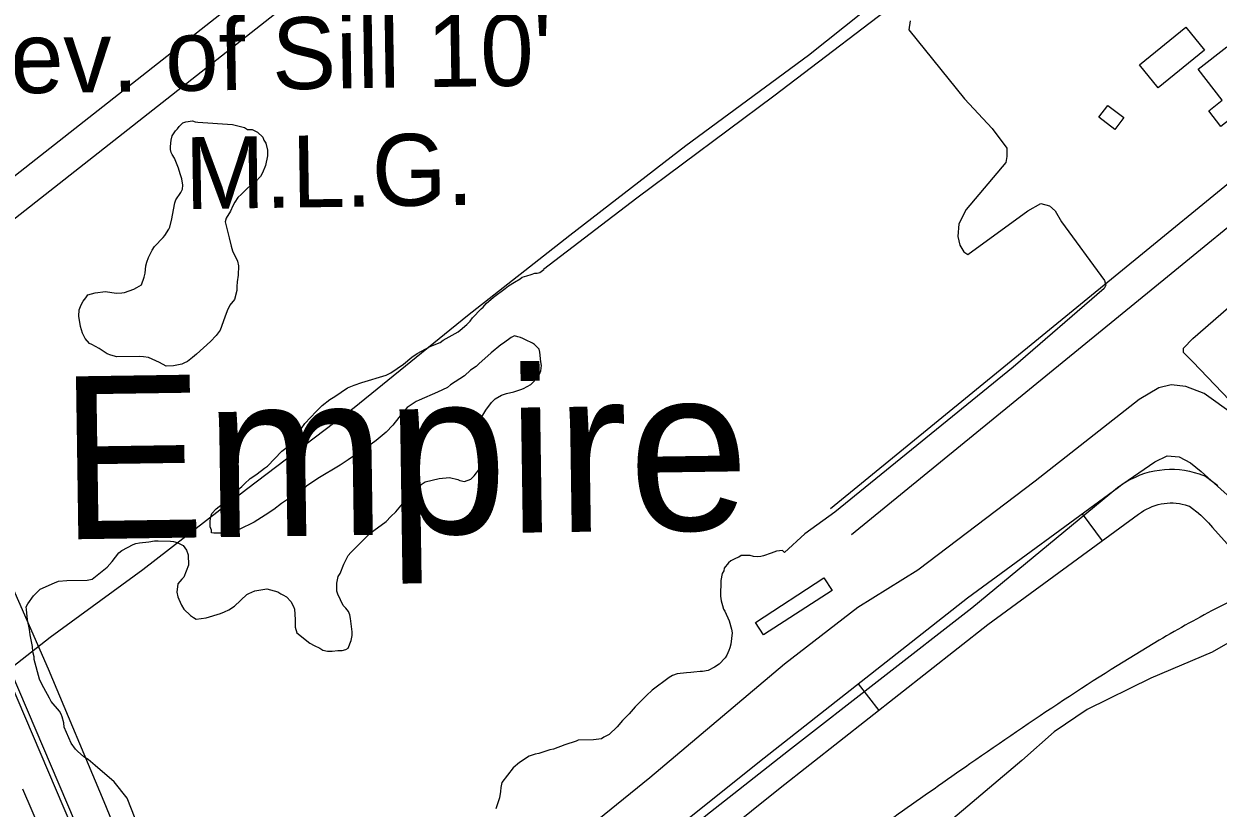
# Model space of a CAD drawing. Extents: x 3812694 to 3850888, y 319753 to 345638.
# Drawn here: x 3831459 to 3832522, y 326802 to 327501 of the extents above; entities that cross this region are included whole.
import ezdxf

# ---------------------------------------------------------------- set-up
doc = ezdxf.new("R2010")
doc.units = 0
for name, color, linetype in [('V-BLDG-OTLN', 7, 'Continuous'), ('V-BRDG-IDEN', 7, 'Continuous'), ('V-BRDG-OTLN', 7, 'Continuous'), ('V-LEVE-TOET', 7, 'Continuous'), ('V-ROAD-CNTR', 7, 'Continuous'), ('V-SITE-VEGE', 7, 'Continuous'), ('V-TOPO-GNAM-IDEN', 7, 'Continuous'), ('V-TOPO-SHOR', 7, 'Continuous')]:
    doc.layers.add(name, color=color, linetype=linetype)

msp = doc.modelspace()

# ---------------------------------------------------------------- linework, layer by layer
at = {"layer": 'V-BLDG-OTLN'}
for points in [[(3832510, 327477.3), (3832468.6, 327443.8), (3832452.2, 327464.1), (3832493.5, 327497.6)], [(3832530, 327480.3), (3832562.3, 327438.9), (3832524.4, 327409.3), (3832513.7, 327423.1), (3832525.8, 327432.6), (3832504.3, 327460.2)], [(3832423.9, 327428), (3832438.2, 327417.1), (3832430.2, 327406.6), (3832415.9, 327417.4)], [(3832178.4, 326996.3), (3832117.4, 326956.7), (3832110.2, 326967.8), (3832171.1, 327007.5)]]:
    msp.add_lwpolyline(points, close=True, dxfattribs=at)
at = {"layer": 'V-BRDG-OTLN'}
for p, q in [((3831436.9, 327025.2), (3831480.5, 326926.4)), ((3831480.5, 326926.4), (3831530.2, 326808.2)), ((3831477.9, 326773.5), (3831458, 326819.2)), ((3831530.2, 326808.2), (3831584.2, 326677.7))]:
    msp.add_line(p, q, dxfattribs=at)
msp.add_lwpolyline([(3831236, 327422.7), (3831370.1, 327104.6), (3831609.5, 326543.2), (3831800.4, 326097), (3832029.2, 325568.9), (3832098.1, 325407.9)], dxfattribs=at)
at = {"layer": 'V-LEVE-TOET'}
for points in [[(3832535.9, 327153), (3832509.7, 327171.6), (3832493.5, 327177.7), (3832480.4, 327179.2), (3832469.4, 327176.7), (3832451.8, 327166.3), (3832359.1, 327093.5), (3832254.7, 327014.3), (3832201.4, 326980.9), (3832136.1, 326930.5), (3832016.1, 326829.5), (3831887.9, 326725.5), (3831747, 326625), (3831636.4, 326537.4), (3831543.7, 326467), (3831519.8, 326450.6), (3831509.2, 326445), (3831499.8, 326441.7), (3831489.2, 326439.6), (3831479.3, 326440.7), (3831463, 326447.6), (3831447.9, 326459.7)], [(3831440.9, 326391.6), (3831464.1, 326361.9), (3831473.2, 326353.8), (3831479.1, 326354.6), (3831506.9, 326372.7), (3831598.5, 326431.3), (3831715.9, 326516.9), (3831807.7, 326594), (3831938, 326695.2), (3832139.7, 326853.6), (3832302.8, 326980.8), (3832432.6, 327087.9), (3832465.8, 327110.7), (3832476.8, 327116), (3832487.5, 327115.3), (3832497.4, 327109.9), (3832506.9, 327102.1), (3832536, 327076)]]:
    msp.add_lwpolyline(points, dxfattribs=at)
at = {"layer": 'V-ROAD-CNTR'}
for p, q in [((3832401.1, 327064.5), (3832418.8, 327040.3)), ((3832201.6, 326913.1), (3832220.1, 326889.5))]:
    msp.add_line(p, q, dxfattribs=at)
for points in [[(3832444.3, 328146.7), (3831373.3, 327304.5)], [(3832462.8, 328123.2), (3831385.9, 327276.2)], [(3832841.6, 327566.6), (3832784, 327544.1), (3832734.9, 327518.3), (3832702.4, 327498.3), (3832461.2, 327301.2), (3832176.9, 327068.9)], [(3832849.5, 327537.5), (3832796.4, 327516.8), (3832749.7, 327492.2), (3832719.8, 327473.8), (3832480.2, 327278), (3832195.8, 327045.7)], [(3832088.4, 325411.4), (3831857.4, 325950.7), (3831227.4, 327429.2)], [(3831938, 326703.2), (3832113.7, 326843.9), (3832299.1, 326989.7), (3832433.5, 327088.3), (3832436.8, 327090.7), (3832440.6, 327093.1), (3832444.5, 327095.3), (3832448.5, 327097.2), (3832452.6, 327099), (3832456.8, 327100.5), (3832461.1, 327101.7), (3832465.5, 327102.7), (3832469.9, 327103.4), (3832474.4, 327103.9), (3832478.8, 327104.1), (3832483.3, 327104.1), (3832487.8, 327103.8), (3832492.2, 327103.2), (3832496.6, 327102.4), (3832500.9, 327101.3), (3832505.2, 327100), (3832510.8, 327097.9), (3832517.2, 327093.3), (3832521.8, 327089.7)], [(3831956.5, 326679.6), (3832132.3, 326820.4), (3832317.2, 326965.8), (3832451.2, 327064), (3832453.8, 327065.9), (3832456.1, 327067.4), (3832458.4, 327068.7), (3832460.9, 327069.9), (3832463.4, 327071), (3832466, 327071.9), (3832468.6, 327072.6), (3832471.3, 327073.2), (3832474, 327073.7), (3832476.7, 327074), (3832479.4, 327074.1), (3832482.1, 327074.1), (3832484.8, 327073.9), (3832487.6, 327073.5), (3832490.2, 327073), (3832492.9, 327072.4), (3832495.5, 327071.6), (3832496.6, 327071.2), (3832499.2, 327069.3), (3832503.3, 327066.1)], [(3832502.8, 327066.5), (3832506.7, 327063.2), (3832510.2, 327059.8), (3832513.5, 327056.4), (3832517, 327052.4), (3832591.6, 326969.5), (3832700.3, 326836.3), (3832727.3, 326802.5)]]:
    msp.add_lwpolyline(points, dxfattribs=at)
msp.add_spline([(3832623.9, 326963.7), (3832590.8, 326992.1), (3832563.6, 326995.7), (3832523.2, 326981.5), (3832469.7, 326951.9), (3832301.2, 326841.8), (3832173.9, 326751.5), (3831994.6, 326614), (3831890.9, 326526.9), (3831841.9, 326487), (3831795.4, 326463.1), (3831786.2, 326461.4)], degree=3, dxfattribs=at)
at = {"layer": 'V-SITE-VEGE'}
for points in [[(3831808, 327164.3), (3831800.2, 327159.1), (3831796.1, 327154.4), (3831787.5, 327143.3), (3831781.5, 327137.2), (3831772.4, 327129.8), (3831762.3, 327122.3), (3831758.7, 327119.9), (3831747.7, 327112.4), (3831740.4, 327107.7), (3831720.7, 327096), (3831710.6, 327089), (3831707.9, 327086.6), (3831688.2, 327073.5), (3831681.3, 327068.4), (3831673.6, 327063.2), (3831663.9, 327057.1), (3831650.7, 327050.5), (3831647, 327049.6), (3831641.5, 327047.7), (3831635, 327047.1), (3831628.1, 327047.1), (3831625.8, 327047.5), (3831625.8, 327049.8), (3831624.8, 327053), (3831624.8, 327058.1), (3831625.2, 327061.8), (3831626.1, 327064.6), (3831630.2, 327068.8), (3831632.9, 327071.1), (3831642.1, 327078.1), (3831644.8, 327081.4), (3831647.5, 327083.7), (3831649.8, 327086), (3831653, 327088.8), (3831655.3, 327091.1), (3831660.3, 327095.8), (3831664.4, 327098.6), (3831666.7, 327100), (3831673.1, 327105.2), (3831675.8, 327107), (3831688.6, 327120.1), (3831693.2, 327123.8), (3831703.2, 327135.5), (3831705.9, 327140.1), (3831709.1, 327144.7), (3831719.1, 327155.5), (3831724.6, 327161), (3831731.4, 327166.2), (3831735.6, 327169), (3831747, 327176.5), (3831753, 327178.9), (3831759.9, 327181.2), (3831781.4, 327187.9), (3831785.6, 327189.8), (3831797, 327197.8), (3831804.3, 327203.9), (3831808.9, 327207.1), (3831819.9, 327213.2), (3831822.6, 327214.2), (3831829.5, 327217), (3831832.3, 327218.9), (3831845.6, 327226.4), (3831847.4, 327227.8), (3831853.3, 327233), (3831856.1, 327235.8), (3831858.3, 327239), (3831866.1, 327246.9), (3831867.9, 327248.3), (3831870.6, 327251.6), (3831877, 327257.2), (3831887.5, 327265.1), (3831890.3, 327267.5), (3831895.8, 327270.8), (3831900.8, 327273.6), (3831902.6, 327275), (3831906.8, 327276.4), (3831910.5, 327277.4), (3831913.7, 327278.8), (3831916, 327278.8), (3831918.3, 327279.3), (3831921.8, 327281.9), (3831921.5, 327282.2), (3832004.7, 327345.8), (3832126.6, 327436.5), (3832252.1, 327532.3)], [(3832247.8, 327503.3), (3832246.9, 327495.2), (3832296.3, 327433.8), (3832321, 327407.6), (3832333.9, 327390), (3832334, 327382.4), (3832333, 327377.3), (3832297.9, 327335.3), (3832291.4, 327322.5)], [(3831509.2, 327231.2), (3831507.7, 327240.4), (3831508.1, 327245.9), (3831509.9, 327250.5), (3831511.7, 327253.8), (3831514, 327256.6), (3831515.8, 327259.4), (3831522.3, 327261.3), (3831531.5, 327262.3), (3831541.2, 327261), (3831546.2, 327261.1), (3831548.5, 327261.6), (3831556.8, 327264.4), (3831559.5, 327265.8), (3831563.7, 327268.2), (3831565.9, 327275.1), (3831566.8, 327278.8), (3831567.6, 327285.3), (3831568.5, 327288.5), (3831569.9, 327292.7), (3831573, 327299.2), (3831575.3, 327302.4), (3831583, 327310.3), (3831584.4, 327312.2), (3831588, 327317.8), (3831588.9, 327319.6), (3831590.7, 327327), (3831591.1, 327330.2), (3831593.3, 327341.3), (3831594.2, 327344.1), (3831598.7, 327350.6), (3831600.1, 327353.4), (3831600.5, 327357.1), (3831599.5, 327362.6), (3831598.1, 327367.2), (3831596.6, 327372.2), (3831592.9, 327381), (3831591, 327384.2), (3831590, 327386), (3831589.5, 327388.8), (3831589.5, 327391.5), (3831589.9, 327397.1), (3831590.8, 327400.8), (3831594, 327405.4), (3831595.8, 327407.3), (3831597.2, 327409.1), (3831600.4, 327412.4), (3831603.1, 327413.3), (3831609.1, 327414.3), (3831611.4, 327413.4), (3831613.7, 327413), (3831644.6, 327411), (3831655.2, 327408.4), (3831658, 327406.6), (3831662.2, 327406.6), (3831666.8, 327404.3), (3831671.5, 327399.8), (3831672.4, 327397), (3831674.3, 327394.3), (3831675.7, 327388.3), (3831675.8, 327383.2), (3831674.1, 327374.5), (3831671.4, 327368), (3831669.5, 327364.7), (3831665, 327360.1), (3831661.3, 327357.3), (3831657.2, 327353.5), (3831652.7, 327348.9), (3831649.5, 327346.1), (3831646.8, 327341.9), (3831644.9, 327338.7), (3831642.7, 327334), (3831639.1, 327327.5), (3831638.2, 327324.3), (3831641.6, 327310), (3831643.5, 327302.7), (3831644.5, 327298.5), (3831649.2, 327289.4), (3831650.1, 327285.2), (3831649.8, 327276.9), (3831648.9, 327270.9), (3831648.5, 327266.8), (3831648.5, 327263.1), (3831646.3, 327255.2), (3831642.2, 327250.1), (3831640, 327245), (3831637.7, 327239.5), (3831633.7, 327227.9), (3831630.1, 327223.3), (3831625.1, 327217.7), (3831612.7, 327206.5), (3831609.1, 327203.7), (3831604.5, 327199.9), (3831601.3, 327198.5), (3831599.5, 327197.6), (3831592.1, 327196.1), (3831585.6, 327196), (3831579.6, 327199.2), (3831569.9, 327203.7), (3831565.3, 327204.1), (3831562, 327204.5)], [(3832291.4, 327322.5), (3832290.5, 327311.3), (3832292.1, 327303.7), (3832295.8, 327297.7), (3832299.3, 327295.2), (3832352.8, 327334.3), (3832364.4, 327340.6), (3832372, 327338.6), (3832377.1, 327334.1), (3832382.8, 327324.5), (3832421, 327272.1), (3832422, 327268), (3832420.6, 327265), (3832339.5, 327195), (3832181, 327065.8)], [(3832610.3, 327083.9), (3832499.7, 327199.7), (3832491.3, 327207.9), (3832491.3, 327212), (3832499.5, 327220.4), (3832583.7, 327293.4)], [(3831562, 327204.5), (3831541.8, 327204.3), (3831536.2, 327205.6), (3831533, 327207), (3831526, 327211.5), (3831519.5, 327215.1), (3831517.2, 327216), (3831513.5, 327220.6), (3831511.1, 327225.2), (3831509.2, 327231.2)], [(3831646.3, 326982.3), (3831657.3, 326992.5), (3831659.1, 326993.5), (3831664.6, 326995.8), (3831675.2, 326997.8), (3831684.9, 326995.1), (3831687.7, 326993.3), (3831689.5, 326992.4), (3831692.8, 326990.6), (3831696.5, 326986.5), (3831698.9, 326981.9), (3831699.8, 326979.6), (3831700.4, 326970.4), (3831700.5, 326963.5), (3831701.9, 326958.4), (3831713.5, 326949.4), (3831717.2, 326947.1), (3831722.3, 326944.8), (3831725.1, 326943), (3831729.3, 326942.1), (3831733.4, 326942.2), (3831738.5, 326942.7), (3831742.2, 326942.7), (3831745.4, 326943.7), (3831747.7, 326944.7), (3831750.4, 326951.6), (3831751.2, 326956.2), (3831751.2, 326959.4), (3831749.7, 326971.4), (3831749.2, 326974.6), (3831747.8, 326977.4), (3831745.4, 326980.6), (3831743.1, 326982.9), (3831738.4, 326993), (3831737.4, 326995.7), (3831737.4, 327002.6), (3831738.7, 327008.6), (3831740.5, 327011.4), (3831743.6, 327019.7), (3831745, 327022.1), (3831747.7, 327027.2), (3831750, 327030), (3831767.3, 327047.2), (3831781.5, 327057.5), (3831785.6, 327062.1), (3831790.1, 327066.3), (3831798.8, 327077), (3831802, 327081.2), (3831812.5, 327090.6), (3831816.1, 327092.9), (3831828.5, 327095.8), (3831837.7, 327096.8), (3831845.1, 327095.1), (3831847, 327094.2), (3831851.2, 327093.3), (3831856.7, 327095.2), (3831859.9, 327098.4), (3831864.9, 327104.9), (3831865.7, 327109.1), (3831866.1, 327117.9), (3831865.6, 327122.5), (3831863.2, 327131.2), (3831863.2, 327134.4), (3831862.7, 327136.7), (3831865.8, 327149.2), (3831870.3, 327156.6), (3831875.3, 327163.6), (3831878.5, 327166.9), (3831884, 327170.1), (3831888.6, 327171.6), (3831895, 327173), (3831901.4, 327175), (3831903.7, 327175.9), (3831910.1, 327179.7), (3831913.3, 327182.5), (3831918.3, 327189.4), (3831919.2, 327191.7), (3831919.6, 327196.4), (3831919.1, 327199.6), (3831918.1, 327208.3), (3831917.6, 327211.1), (3831913.4, 327215.2), (3831911.6, 327216.5), (3831905.6, 327219.2), (3831903.2, 327220.6), (3831900.9, 327221.5), (3831898.6, 327221.9), (3831895.8, 327222.8), (3831892.6, 327221.4), (3831885.8, 327216.3), (3831883.5, 327214.9), (3831874.8, 327207.8), (3831863.8, 327198), (3831861.6, 327195.7), (3831856.5, 327192.4), (3831851.1, 327187.3), (3831838.7, 327179.3), (3831836, 327177), (3831827.2, 327172.8), (3831810.7, 327165.7), (3831808, 327164.3)], [(3832181, 327065.8), (3832154.2, 327046.7), (3832136, 327029.9), (3832134.4, 327031.8), (3832128.9, 327031.3), (3832124.3, 327029.4), (3832117.4, 327027), (3832115.1, 327026.5), (3832111.9, 327026.1), (3832108.6, 327026.5), (3832105.4, 327027.4), (3832097.6, 327027.3), (3832095.3, 327025.9), (3832093, 327024.9), (3832088.4, 327022.6), (3832086.1, 327020.7), (3832082.5, 327016.1), (3832082, 327013.7), (3832080.7, 327011.4), (3832079.4, 327005), (3832079, 326991.1), (3832079.6, 326987), (3832081, 326982.8), (3832081.9, 326979.6), (3832082.9, 326977.8), (3832086.7, 326969.1), (3832089, 326961.7), (3832089.5, 326958.5), (3832088.3, 326948.4), (3832087.4, 326945.1), (3832086.5, 326942.8), (3832084.7, 326938.6), (3832083.3, 326936.3), (3832077.9, 326930.7), (3832073.7, 326927.9), (3832068.2, 326925.1), (3832063.2, 326924.1), (3832060.9, 326924.1), (3832055.4, 326923.6), (3832052.6, 326923.1), (3832048.9, 326923), (3832040.6, 326922), (3832036.5, 326920.6), (3832033.3, 326918.7), (3832018.2, 326907.5), (3832013.2, 326902.8), (3832003.1, 326892.6), (3831997.7, 326886.5), (3831994.9, 326883.3), (3831991.8, 326880.5), (3831987.2, 326874.9), (3831985.4, 326873), (3831981.7, 326869.8), (3831979.9, 326867.9), (3831975.3, 326865.5), (3831973, 326864.1), (3831966.1, 326863.1), (3831952.3, 326863), (3831950.5, 326862), (3831940.4, 326858.7), (3831930.3, 326854.9), (3831927, 326854.4), (3831917.4, 326851.1), (3831914.2, 326850.6), (3831908.7, 326848.7), (3831900, 326843.1), (3831894.5, 326838.4), (3831884.5, 326825.4), (3831883.6, 326820.8), (3831883.2, 326817.1), (3831882.3, 326811.5), (3831879.2, 326801.8)], [(3831561.2, 326784.9), (3831550.9, 326811.3), (3831539.2, 326825.9), (3831522.5, 326840.3), (3831516, 326845.8), (3831512.3, 326848.1), (3831506.7, 326853.1), (3831504.8, 326854.9), (3831501.1, 326860.4), (3831494.9, 326874.6), (3831494.4, 326878.3), (3831493, 326883.8), (3831492, 326886.1), (3831490.6, 326888.9), (3831483.2, 326897.5), (3831481.7, 326900.3), (3831479.9, 326903.5), (3831475.2, 326912.2), (3831472.8, 326917.2), (3831468, 326934.7), (3831468, 326937), (3831467, 326941.6), (3831466.5, 326946.2), (3831464.5, 326956.8), (3831464, 326961.4), (3831462.1, 326970.1), (3831461.1, 326979.3), (3831461, 326981.6), (3831462.4, 326984.4), (3831467.4, 326991.4), (3831473.3, 326997.4), (3831486.2, 327003.1), (3831489.8, 327004.5), (3831497.2, 327005.1), (3831515.2, 327005.3), (3831519.8, 327006.2), (3831533, 327017), (3831537.6, 327022.1), (3831543.5, 327029.6), (3831546.2, 327031.9), (3831556.3, 327037.1), (3831558.6, 327038), (3831561.8, 327038.5), (3831570.1, 327039.5), (3831575.2, 327040.5), (3831578.4, 327040.5), (3831589.5, 327040.2), (3831592.2, 327039.8), (3831595.5, 327038.9), (3831600.6, 327036.2), (3831603.8, 327032), (3831605.3, 327027.9), (3831605.4, 327018.7), (3831601.3, 327008.1), (3831599.5, 327006.2), (3831595.9, 327002), (3831595, 326994.6), (3831596, 326990.5), (3831596.9, 326988.6), (3831599.3, 326983.1), (3831601.2, 326979.5), (3831607.2, 326974), (3831610, 326972.2), (3831612.3, 326970.8), (3831621.1, 326971.9), (3831634, 326975.7), (3831637.6, 326977.1), (3831641.3, 326979), (3831646.3, 326982.3)]]:
    msp.add_lwpolyline(points, dxfattribs=at)
at = {"layer": 'V-TOPO-SHOR'}
for points in [[(3832611.7, 327822.1), (3832543, 327773.3), (3832452.8, 327704.6), (3832368.1, 327639.9), (3832269.7, 327562.1), (3832157.3, 327472.3), (3832048.3, 327392), (3831944.9, 327312.1), (3831853.9, 327240.7), (3831752.9, 327158.9), (3831657.2, 327086.2), (3831564.7, 327014.7), (3831482.3, 326954.4), (3831387.8, 326880.5), (3831316.8, 326823.1)], [(3832567.6, 326970.3), (3832516.9, 326941.3), (3832462.1, 326918.2), (3832405.5, 326890.3), (3832376.1, 326870.5), (3832347.4, 326844.7), (3832278.1, 326786.5)]]:
    msp.add_lwpolyline(points, dxfattribs=at)

# ---------------------------------------------------------------- texts
at = {"layer": 'V-BRDG-IDEN'}
for s, p in [("Elev. of Sill 10'", (3831371, 327437.5)), ('M.L.G.', (3831602.7, 327335.6))]:
    msp.add_text(s, height=64, rotation=0.8667, dxfattribs=at).set_placement(p)
at = {"layer": 'V-TOPO-GNAM-IDEN'}
msp.add_text('Empire', height=145, rotation=0.8434, dxfattribs=at).set_placement((3831491.5, 327041.6))

doc.saveas('drawing.dxf')
